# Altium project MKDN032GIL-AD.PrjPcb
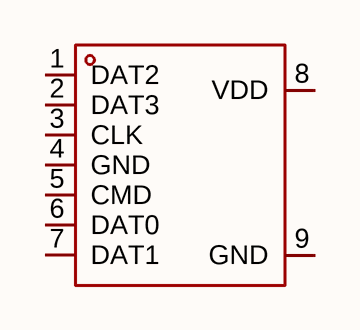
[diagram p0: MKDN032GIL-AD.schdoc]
1 sheet, 1 parts. Net scope: global (net labels, ports and power ports of the same name join across sheets).

## Sheet MKDN032GIL-AD.schdoc
size 127 x 101 mm

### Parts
U?  mkdn032gil-ad  [LGA-16_L12.5-W9.0-P1.27-TL-EP]  (value not drawn)

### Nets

Not connected (* = marked no-connect by the designer): U? 1(DAT2) 2(DAT3) 3(CLK) 4(GND) 5(CMD) 6(DAT0) 7(DAT1) 8(VDD) 9(GND)

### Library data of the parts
U? = mkdn032gil-ad: 存储容量:32Gbit;时钟频率(fc):50MHz;工作电压:2.7V~3.6V;; Manufacturer: MK(米客方德); AddInBom: yes; ModelId: aae4acadbbb4480ebd429fe2f08c27d7; ModelTransform: 492.125,354.33,0,0,0,0,0,0,0; Memory Size: 32Gbit; Interface: SD接口; Clock Frequency: 50MHz; Standby Supply Current: 80uA; Program / Erase Cycles: 5万次; ECC: 有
